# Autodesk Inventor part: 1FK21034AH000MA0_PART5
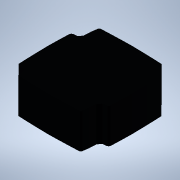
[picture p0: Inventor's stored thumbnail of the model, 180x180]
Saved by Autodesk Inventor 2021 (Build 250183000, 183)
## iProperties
Created: 2025-04
Part Number: 1FK21034AH000MA0_PART5
Material: Generic
Catalog Web Link: www.3dfindit.com
Description: -Servo synchronous motor
Document SubType Name: Modeling
Designer: psAdmin
Mass: 81.3964 g
Surface Area: 120.819 cm^2
Volume: 81.3964 cm^3
Density: 1 g/cm^3
Appearance: PSOLRGB-38-46-56
Category: PARTsolutions
Title: 1FK21034AH000MA0_PART5
Author: Cadenas PARTsolutions
Comments: Servo synchronous motor
Sending System: PARTsolutions
Preprocessor: ST-DEVELOPER v19.3
PSOL_IDENT_0: {$CADENAS_DATA/23d-libs/siemens_ag/_cat_/ec/b7/1fk21034ah000ma0.prj},213 {VTYP=3D},{NB=1FK21034AH000
PSOL_IDENT_1: MA0_PART5},{LINA=1FK21034AH000MA0_PART5},{NN=1FK21034AH000MA0_PART5},{NOPRJ=TRUE},{DATE=19.08.2025 1
PSOL_IDENT_2: 4:01:05},{GEOMDATE=30.07.2025 02:01:02},{VERSION=},{LINEID=10},{WBVAR=},{WBNUMERIC=}  {NB=1FK21034AH
PSOL_IDENT_3: 000MA0_PART5},{LINA=1FK21034AH000MA0_PART5},{KT=DUMMY},{PREVIEW=../../../_pool_/7c/50/p_d211_xx_0093
PSOL_IDENT_4: 2j.png},{DESCSHORT=SIMOTICS S-1FK2 HD, SINAMICS S210 3AC 400V-480V, 1.01 Nm, 4500 rpm},{DESCLONG=SIM
PSOL_IDENT_5: OTICS S-1FK2 HD servo motor M0=1.27 Nm; PN = 0.48 kW at nN=4500 rpm (380-480 V); PN = 0.3 kW at nN=2
PSOL_IDENT_6: 500 rpm (200-240 V); degree of protection IP64; cylindrical shaft D14 x 30 mm; absolute encoder 22-b
PSOL_IDENT_7: it + 12-bit multiturn (encoder AM22DQC); with OCC interface; plug size M17, rotatable; SIMOTICS S-1F
PSOL_IDENT_8: K2 servomotorfor a wide range of uses in industrial environments. SIMOTICS S‑1FK2 servomotors are co
PSOL_IDENT_9: mpact synchronous motors with a high dynamic performance that set themselves apart as a result of th
PSOL_IDENT_10: eir high power density, degree of protection and overload capability. The motors are available in tw
PSOL_IDENT_11: o variants: as High Dynamic variant (highest dynamic performance as a result of the low intrinsic mo
PSOL_IDENT_12: ment of inertia for applications demanding a high dynamic performance with low moved masses) - and a
PSOL_IDENT_13: s Compact variant (precise and stable closed-loop control for medium up to large moved masses as a r
PSOL_IDENT_14: esult of a medium intrinsic moment of inertia). SIMOTICSS‑1FK2 servomotors fully exploit their stren
PSOL_IDENT_15: gths in a system with the SINAMICSS210 frequency converter and simple connection using the one cable
PSOL_IDENT_16: connection (OCC). Advantages include the short control and positioning times, fast and precise corr
PSOL_IDENT_17: ection of disturbing quantities as well as stable control with a high dynamic performance. The servo
PSOL_IDENT_18: motors can be configured to address a wide range of requirements. For example with and without hold
PSOL_IDENT_19: ing brake, IP64 or IP65 degree of protection, singleturn or multiturn absolute encoders - to name ju
PSOL_IDENT_20: st a few. Further, the servomotors are available in different shaft heights extending from 20 to 100
PSOL_IDENT_21: . A shaft sealing ring is available to achieve an IP65 degree of protection and for subsequent mount
PSOL_IDENT_22: ing at the motor or as spare part. SIMOTICS - the optimum motor for each and every motion control ap
PSOL_IDENT_23: plication.},{INTNO=4034106444822},{SUPPLIERALTNO=1FK2103-4AH00-0MA0},{MANUID=1FK21034AH000MA0},{MANU
PSOL_IDENT_24: NAME=Siemens},{MANUTYPEDESC=SYNCHRONOUS MOTOR 1FK2 HD 1,27 NM},{AAU732=SIMOTICS},{AAO057=S-1FK2},{AA
PSOL_IDENT_25: U734=SIMOTICS S-1FK2 HD servo motor M0=1.27 Nm; PN = 0.48 kW at nN=4500 rpm (380-480 V); PN = 0.3 kW
PSOL_IDENT_26: at nN=2500 rpm (200-240 V); degree of protection IP64; cylindrical shaft D14 x 30 mm; absolute enco
PSOL_IDENT_27: der 22-bit + 12-bit multiturn (encoder AM22DQC); with OCC interface; plug size M17, rotatable;},{AAW
PSOL_IDENT_28: 338=SYNCHRONOUS MOTOR 1FK2 HD 1,27 NM},{AAO742=SIMOTICS},{AAO663=4034106444822},{NOCUPEROU=1},{PRICE
PSOL_IDENT_29: QUANTITY=1},{QUANTITYMIN=1},{QUANTITYINT=1},{CTN=85015100},{COO=RO},{AAO676=1FK2103-4AH00-0MA0},{AAO
PSOL_IDENT_30: 677=Siemens AG},{ORDERUNIT=C62},{CONTENTUNIT=C62}
NB: 1FK21034AH000MA0_PART5
NT: Servo synchronous motor
NBSYN: $MANUID._PART5
LINA: 1FK21034AH000MA0_PART5
CATALOG: SIEMENS
PREVIEW: ../../../_pool_/7c/50/p_d211_xx_00932j.png
DESCSHORT: SIMOTICS S-1FK2 HD, SINAMICS S210 3AC 400V-480V, 1.01 Nm, 4500 rpm
DESCLONG: SIMOTICS S-1FK2 HD servo motor M0=1.27 Nm; PN = 0.48 kW at nN=4500 rpm (380-480 V); PN = 0.3 kW at nN=2500 rpm (200-240 V); degree of protection IP64; cylindric
INTNO: 4034106444822
SUPPLIERALTNO: 1FK2103-4AH00-0MA0
MANUID: 1FK21034AH000MA0
MANUNAME: Siemens
MANUTYPEDESC: SYNCHRONOUS MOTOR 1FK2 HD 1,27 NM
AAU732: SIMOTICS
AAO057: S-1FK2
AAU734: SIMOTICS S-1FK2 HD servo motor M0=1.27 Nm; PN = 0.48 kW at nN=4500 rpm (380-480 V); PN = 0.3 kW at nN=2500 rpm (200-240 V); degree of protection IP64; cylindric
AAW338: SYNCHRONOUS MOTOR 1FK2 HD 1,27 NM
AAO742: SIMOTICS
AAO663: 4034106444822.0
NOCUPEROU: 1
PRICEQUANTITY: 1
QUANTITYMIN: 1
QUANTITYINT: 1
CTN: 85015100
COO: RO
ARTICLENO: 1FK21034AH000MA0_PART5
BOMINFO: 1FK21034AH000MA0_PART5
CREATOR: CADENAS GmbH
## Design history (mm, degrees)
feature "2025_04_17_15_01_37_0220"
body "Solid1"
